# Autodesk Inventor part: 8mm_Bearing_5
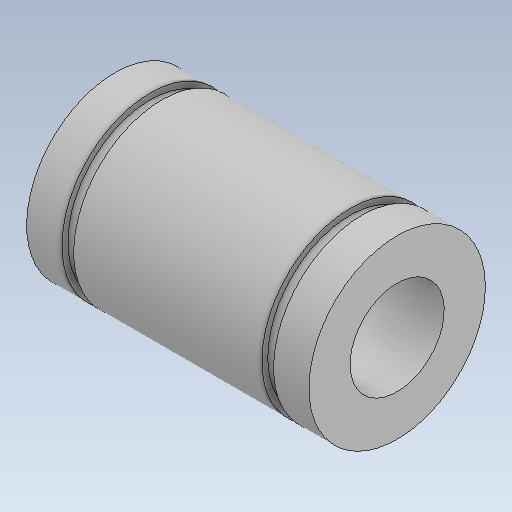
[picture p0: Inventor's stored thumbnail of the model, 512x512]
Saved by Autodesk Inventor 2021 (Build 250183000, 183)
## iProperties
Created: 2026-10
Part Number: 8mm_Bearing_5
Material: Generic
Document SubType Name: Modeling
Designer: hp
Density: 1 g/cm^3
Appearance: Default
Author: hp
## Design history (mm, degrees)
feature "Body1"
body "Solid1"
